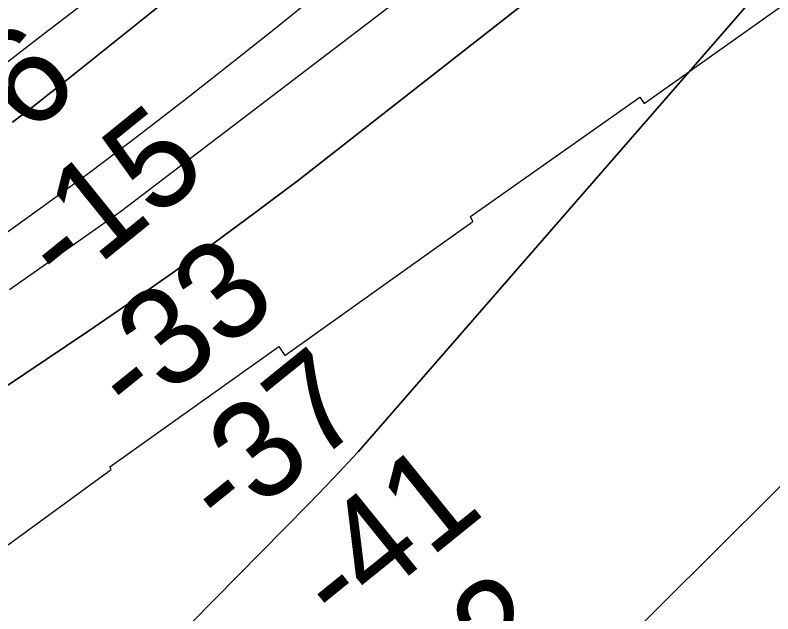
# Model space of a CAD drawing. Extents: x 3324104 to 3361979, y 612876 to 638273.
# Drawn here: x 3351732 to 3352253, y 619719 to 620131 of the extents above; entities that cross this region are included whole.
import ezdxf

# ---------------------------------------------------------------- set-up
doc = ezdxf.new("R2010")
doc.units = 0
for name, color, linetype in [('V-RIVR-EDGE', 7, 'Continuous'), ('V-RIVR-RANG', 7, 'Continuous'), ('V-RRAP-RVMT', 7, 'Continuous'), ('V-TOPO-DPTH', 7, 'Continuous'), ('V-TOPO-MAJR', 7, 'Continuous'), ('V-TOPO-MINR', 7, 'Continuous')]:
    doc.layers.add(name, color=color, linetype=linetype)

msp = doc.modelspace()

# ---------------------------------------------------------------- linework, layer by layer
at = {"layer": 'V-RIVR-EDGE'}
msp.add_spline([(3356051.95, 622889.63), (3356029.15, 622881.43), (3356012.46, 622875.66), (3355994.6, 622867.17), (3355977.52, 622859.07), (3355958.5, 622850.97), (3355948.4, 622843.24), (3355934.03, 622834.75), (3355904.12, 622817.76), (3355878.1, 622802.31), (3355856.74, 622790.34), (3355829.95, 622776.44), (3355805.11, 622765.65), (3355764.72, 622744.81), (3355744.14, 622733.61), (3355694.06, 622710.85), (3355668.43, 622698.12), (3355641.64, 622685), (3355605.15, 622669.19), (3355569.44, 622657.26), (3355539.17, 622646.47), (3355510.83, 622636.85), (3355482.11, 622628.39), (3355461.93, 622623.01), (3355442.52, 622614.14), (3355422.73, 622607.21), (3355409.53, 622603.36), (3355388.97, 622597.59), (3355371.88, 622589.49), (3355348.98, 622581.02), (3355297.71, 622547.02), (3355260.04, 622525.78), (3355211.1, 622494.49), (3355190.13, 622484.46), (3355184.7, 622482.92), (3355179.26, 622477.89), (3355174.21, 622475.58), (3355160.62, 622470.96), (3355143.54, 622463.63), (3355133.06, 622457.07), (3355125.67, 622450.49), (3355113.25, 622443.93), (3355096.93, 622433.11), (3355081.02, 622426.95), (3355064.32, 622419.23), (3355056.95, 622418.86), (3355048.8, 622414.62), (3355041.8, 622406.88), (3355036.76, 622406.5), (3355031.32, 622405.74), (3355027.05, 622404.2), (3355017.34, 622396.08), (3355010.74, 622394.93), (3355001.42, 622388.36), (3354988.6, 622379.09), (3354972.29, 622369.43), (3354947.44, 622356.31), (3354937.73, 622351.68), (3354926.08, 622343.56), (3354903.15, 622326.56), (3354891.11, 622318.06), (3354883.33, 622307.22), (3354879.44, 622304.12), (3354875.17, 622302.58), (3354867.8, 622299.11), (3354853.03, 622288.29), (3354842.54, 622279.01), (3354826.61, 622267.41), (3354807.2, 622259.71), (3354793.23, 622255.47), (3354765.68, 622249.73), (3354748.61, 622245.5), (3354734.63, 622239.33), (3354712.11, 622227.37), (3354697.74, 622218.87), (3354685.31, 622209.98), (3354640.65, 622184.5), (3354622.01, 622176.01), (3354616.19, 622175.25), (3354603.38, 622167.52), (3354578.92, 622157.11), (3354554.46, 622147.48), (3354537.39, 622142.87), (3354530.78, 622137.84), (3354500.11, 622122.79), (3354463.61, 622102.33), (3354417.79, 622078.79), (3354386.33, 622060.64), (3354340.11, 622032.44), (3354321.08, 622021.25), (3354284.96, 621998.84), (3354257, 621982.24), (3354217, 621958.68), (3354194.08, 621942.84), (3354176.99, 621931.63), (3354157.57, 621921.98), (3354141.64, 621910.39), (3354135.42, 621904.2), (3354130.36, 621897.62), (3354120.65, 621891.05), (3354103.96, 621882.95), (3354075.58, 621856.65), (3354044.89, 621835.39), (3354013.04, 621812.21), (3353971.47, 621781.67), (3353947.77, 621763.5), (3353941.17, 621763.52), (3353935.35, 621762.76), (3353929.53, 621760.06), (3353924.87, 621756.58), (3353920.59, 621751.55), (3353917.08, 621742.64), (3353910.48, 621741.49), (3353904.66, 621738.4), (3353893.78, 621731.06), (3353879.8, 621721.4), (3353866.19, 621708.64), (3353854.92, 621697.42), (3353843.26, 621687.75), (3353839.77, 621688.54), (3353831.23, 621686.23), (3353823.08, 621681.21), (3353818.03, 621677.34), (3353800.94, 621666.14), (3353790.85, 621663.06), (3353781.91, 621654.94), (3353777.63, 621651.85), (3353776.07, 621648.75), (3353775.67, 621643.71), (3353772.18, 621641), (3353755.87, 621632.13), (3353735.68, 621622.09), (3353718.58, 621608.17), (3353704.21, 621600.45), (3353694.12, 621596.6), (3353683.64, 621592.36), (3353671.21, 621584.25), (3353642.07, 621562.99), (3353598.95, 621534.01), (3353578.37, 621522.43), (3353556.23, 621507.75), (3353547.68, 621501.95), (3353525.93, 621489.21), (3353513.12, 621481.09), (3353497.18, 621468.34), (3353476.98, 621450.94), (3353453.28, 621436.65), (3353435.8, 621424.67), (3353404.72, 621401.09), (3353378.3, 621380.21), (3353361.59, 621368.62), (3353339.46, 621355.1), (3353319.65, 621342.35), (3353299.45, 621329.99), (3353283.54, 621324.6), (3353273.05, 621317.65), (3353254.77, 621295.98), (3353236.88, 621275.47), (3353219.39, 621258.83), (3353195.69, 621241.44), (3353168.49, 621221.34), (3353137.81, 621201.64), (3353112.17, 621185.03), (3353065.55, 621151.79), (3353022.05, 621122.82), (3352993.29, 621100.39), (3352956, 621073.34), (3352907.05, 621037.78), (3352853.8, 620991.77), (3352787.76, 620942.29), (3352749.68, 620913.3), (3352736.85, 620900.92), (3352733.34, 620892.79), (3352728.67, 620886.59), (3352718.96, 620881.19), (3352691.78, 620864.58), (3352660.31, 620841.78), (3352640.5, 620828.25), (3352623.39, 620811.23), (3352605.12, 620792.27), (3352593.46, 620783), (3352582.59, 620778.76), (3352566.29, 620771.43), (3352548.04, 620764.49), (3352522.41, 620750.98), (3352494.45, 620735.54), (3352482.41, 620727.04), (3352479.3, 620723.17), (3352476.96, 620717.36), (3352470.74, 620711.94), (3352455.99, 620707.33), (3352443.18, 620700.38), (3352419.1, 620685.7), (3352392.3, 620669.09), (3352362.78, 620650.94), (3352339.08, 620634.32), (3352315.38, 620615.38), (3352284.68, 620590.63), (3352258.65, 620571.31), (3352228.74, 620550.05), (3352193.39, 620527.65), (3352156.88, 620504.86), (3352131.63, 620487.47), (3352093.95, 620462.36), (3352049.28, 620432.99), (3351990.23, 620391.26), (3351936.63, 620357.26), (3351851.55, 620293.87), (3351833.29, 620281.51), (3351816.98, 620273.79), (3351794.06, 620257.95), (3351767.65, 620240.95), (3351719.86, 620206.17), (3351680.63, 620177.57), (3351657.32, 620160.56), (3351637.11, 620145.87), (3351623.13, 620135.44), (3351603.32, 620124.24), (3351588.57, 620120.01), (3351567.22, 620109.59), (3351552.08, 620103.43), (3351538.1, 620096.48), (3351523.73, 620086.43), (3351510.91, 620076.38), (3351503.52, 620069.81), (3351495.35, 620057.42), (3351486, 620042.32), (3351479.39, 620032.64), (3351469.67, 620022.58), (3351448.3, 620006.34), (3351431.59, 619994.75), (3351404.78, 619973.88), (3351377.97, 619951.84), (3351358.93, 619936.37), (3351332.12, 619915.5), (3351306.08, 619892.29), (3351274.58, 619858.25), (3351238.83, 619826.92), (3351215.12, 619805.65), (3351171.59, 619767.75), (3351145.54, 619739.51), (3351124.55, 619722.11), (3351105.9, 619707.81), (3351089.59, 619696.99), (3351079.49, 619691.2), (3351074.04, 619683.45), (3351058.1, 619666.43), (3351043.34, 619655.22), (3351015.36, 619633.96), (3350999.05, 619623.14), (3350992.05, 619617.34), (3350979.23, 619606.13), (3350966.01, 619594.53), (3350951.25, 619582.15), (3350935.7, 619567.84), (3350923.26, 619555.08), (3350910.05, 619544.25), (3350888.29, 619528.02), (3350846.74, 619504.08), (3350821.49, 619490.18), (3350811.39, 619483.61), (3350805.96, 619480.52), (3350800.9, 619473.16), (3350797.41, 619473.17), (3350793.92, 619474.35), (3350788.88, 619473.58), (3350786.93, 619472.04), (3350785.37, 619467.39), (3350785.36, 619462.73), (3350779.53, 619456.15), (3350765.93, 619445.72), (3350746.11, 619428.7), (3350722.4, 619408.98), (3350716.19, 619407.06), (3350713.08, 619403.96), (3350711.13, 619396.99), (3350708.79, 619391.57), (3350704.52, 619391.58), (3350693.26, 619385.79), (3350686.65, 619379.6), (3350679.64, 619368.37), (3350661.38, 619354.45), (3350648.56, 619344.4), (3350645.46, 619344.8), (3350638.47, 619339.39), (3350623.32, 619330.5), (3350616.33, 619326.26), (3350602.35, 619317.37), (3350598.83, 619308.85), (3350582.91, 619299.19), (3350553.77, 619276), (3350526.18, 619255.51), (3350493.55, 619231.94), (3350474.9, 619219.57), (3350474.5, 619213.76), (3350470.22, 619207.17), (3350458.96, 619202.55), (3350446.14, 619194.05), (3350441.09, 619189.79), (3350438.76, 619186.31), (3350434.48, 619180.89), (3350414.67, 619167.76), (3350401.46, 619159.26), (3350384.75, 619146.89), (3350369.6, 619133.74), (3350356.39, 619125.24), (3350350.95, 619119.05), (3350347.43, 619109.36), (3350338.1, 619097.75), (3350324.88, 619083.82), (3350308.55, 619069.9), (3350300.39, 619062.56), (3350296.13, 619062.57), (3350291.47, 619062.19), (3350274.77, 619050.6), (3350258.45, 619037.45), (3350251.84, 619032.81), (3350244.08, 619029.34), (3350233.61, 619028.21), (3350227.39, 619024.34), (3350220.39, 619016.99), (3350213, 619007.32), (3350202.12, 618996.87), (3350193.57, 618989.52), (3350179.6, 618985.29), (3350173.77, 618980.65), (3350164.84, 618977.96), (3350162.12, 618975.25), (3350159.39, 618971.38), (3350154.33, 618963.64), (3350145.78, 618953.19), (3350125.96, 618938.11), (3350102.66, 618923.05), (3350094.5, 618918.41), (3350086.34, 618913), (3350075.07, 618901.01), (3350064.19, 618892.12), (3350039.32, 618873.57), (3350021.84, 618861.59), (3350002.03, 618848.84), (3349991.94, 618844.21), (3349964.36, 618826.44), (3349938.72, 618807.11), (3349915.41, 618792.82), (3349892.5, 618778.92), (3349868.02, 618761.91), (3349852.49, 618753.03), (3349842.79, 618749.95), (3349830.35, 618739.13), (3349804.32, 618720.19), (3349777.9, 618697.76), (3349751.86, 618677.66), (3349729.72, 618661.43), (3349703.69, 618642.88), (3349678.84, 618629.75), (3349648.93, 618611.99), (3349624.46, 618594.99), (3349592.61, 618575.67), (3349570.48, 618564.87), (3349549.5, 618548.63), (3349505.21, 618518.11), (3349479.19, 618499.94), (3349471.42, 618494.53), (3349458.99, 618487.59), (3349438.4, 618472.12), (3349412.37, 618452.41), (3349379.73, 618429.61), (3349350.21, 618410.29), (3349303.2, 618374.73), (3349277.56, 618357.73), (3349263.97, 618347.29), (3349241.43, 618330.68), (3349226.67, 618319.85), (3349207.25, 618306.33), (3349193.17, 618293.54)], degree=3, dxfattribs=at)
at = {"layer": 'V-RRAP-RVMT'}
for p, q in [((3352164.48, 620070.17), (3352294.24, 620162.59)), ((3352044.88, 619992.52), (3352161.38, 620074.41)), ((3352161.38, 620074.41), (3352164.48, 620070.17)), ((3351917.24, 619896.96), (3352046.53, 619989.05)), ((3352046.53, 619989.05), (3352044.88, 619992.52)), ((3351796.76, 619820.47), (3351913.05, 619903.04)), ((3351913.05, 619903.04), (3351917.24, 619896.96)), ((3351672.84, 619727.74), (3351797.82, 619818.44)), ((3351797.82, 619818.44), (3351796.76, 619820.47))]:
    msp.add_line(p, q, dxfattribs=at)
at = {"layer": 'V-TOPO-DPTH'}
for points in [[(3353036.22, 620942.67), (3353003.24, 620918.6), (3352970.44, 620894.29), (3352937.91, 620869.63), (3352905.55, 620844.72), (3352459.62, 620497.61), (3352447.34, 620488.04), (3352435.06, 620478.45), (3352422.8, 620468.85), (3352410.55, 620459.24), (3352392.25, 620444.85), (3352389.16, 620442.42), (3352386.06, 620440), (3352382.95, 620437.58), (3352379.85, 620435.17), (3352360.2, 620419.92), (3352347.25, 620409.91), (3352334.29, 620399.91), (3352321.3, 620389.95), (3352308.3, 620380), (3351805.13, 619996.41), (3351799.27, 619992.18), (3351793.38, 619988), (3351727.81, 619942.08)], [(3353036.22, 620942.67), (3353003.24, 620918.6), (3352970.44, 620894.29), (3352937.91, 620869.63), (3352905.55, 620844.72), (3352459.62, 620497.61), (3352447.34, 620488.04), (3352435.06, 620478.45), (3352422.8, 620468.85), (3352410.55, 620459.24), (3352392.25, 620444.85), (3352389.16, 620442.42), (3352386.06, 620440), (3352382.95, 620437.58), (3352379.85, 620435.17), (3352360.2, 620419.92), (3352347.25, 620409.91), (3352334.29, 620399.91), (3352321.3, 620389.95), (3352308.3, 620380), (3351805.13, 619996.41), (3351799.27, 619992.18), (3351793.38, 619988), (3351727.81, 619942.08)], [(3351729.95, 620057.28), (3351738.1, 620063.46), (3351746.22, 620069.68), (3351754.27, 620075.98), (3351762.28, 620082.33), (3352225.26, 620452.7), (3352240.9, 620465.17), (3352256.58, 620477.61), (3352272.29, 620490), (3352288.03, 620502.36), (3352318.27, 620526.01), (3352318.91, 620526.51), (3352319.56, 620527), (3352320.87, 620527.97), (3352333.79, 620537.38), (3352340.91, 620542.55), (3352348.06, 620547.69), (3352355.23, 620552.8), (3352362.42, 620557.89), (3352890.31, 620929.69)], [(3352890.31, 620929.69), (3352362.42, 620557.89), (3352355.23, 620552.8), (3352348.06, 620547.69), (3352340.91, 620542.55), (3352333.79, 620537.38), (3352320.87, 620527.97), (3352319.56, 620527), (3352318.91, 620526.51), (3352318.27, 620526.01), (3352288.03, 620502.36), (3352272.29, 620490), (3352256.58, 620477.61), (3352240.9, 620465.17), (3352225.26, 620452.7), (3351762.28, 620082.33), (3351754.27, 620075.98), (3351746.22, 620069.68), (3351738.1, 620063.46), (3351729.95, 620057.28)], [(3351319.54, 619603.27), (3351781.82, 619913.5), (3351810.88, 619933.33), (3351839.73, 619953.46), (3351868.26, 619974.03), (3351896.58, 619994.91), (3351926.72, 620017.49), (3352384.5, 620375.72), (3352401.28, 620388.9), (3352418.1, 620402.03), (3352434.99, 620415.07), (3352451.93, 620428.05), (3352740.22, 620647.74), (3352784.16, 620681.15), (3352828.16, 620714.49), (3352872.24, 620747.72), (3352916.37, 620780.89), (3352986.62, 620833.56), (3352995.68, 620840.32), (3353004.75, 620847.07), (3353013.86, 620853.78)], [(3351319.54, 619603.27), (3351781.82, 619913.5), (3351810.88, 619933.33), (3351839.73, 619953.46), (3351868.26, 619974.03), (3351896.58, 619994.91), (3351926.72, 620017.49), (3352384.5, 620375.72), (3352401.28, 620388.9), (3352418.1, 620402.03), (3352434.99, 620415.07), (3352451.93, 620428.05), (3352740.22, 620647.74), (3352784.16, 620681.15), (3352828.16, 620714.49), (3352872.24, 620747.72), (3352916.37, 620780.89), (3352986.62, 620833.56), (3352995.68, 620840.32), (3353004.75, 620847.07), (3353013.86, 620853.78)], [(3353026.28, 620776.91), (3353006.59, 620763.44), (3352605.8, 620491.3), (3352578.11, 620472.26), (3352550.57, 620453.01), (3352523.25, 620433.44), (3352496.08, 620413.65), (3352446.4, 620377.03), (3352444.2, 620375.38), (3352442.02, 620373.71), (3352439.87, 620372), (3352437.74, 620370.27), (3351967.68, 619830.77), (3351950.86, 619812.91), (3351933.84, 619795.24), (3351916.69, 619777.68), (3351644.56, 619502.13)], [(3351644.56, 619502.13), (3351916.69, 619777.68), (3351933.84, 619795.24), (3351950.86, 619812.91), (3351967.68, 619830.77), (3352437.74, 620370.27), (3352439.87, 620372), (3352442.02, 620373.71), (3352444.2, 620375.38), (3352446.4, 620377.03), (3352496.08, 620413.65), (3352523.25, 620433.44), (3352550.57, 620453.01), (3352578.11, 620472.26), (3352605.8, 620491.3), (3353006.59, 620763.44), (3353026.28, 620776.91)]]:
    msp.add_lwpolyline(points, dxfattribs=at)
at = {"layer": 'V-TOPO-MAJR'}
msp.add_lwpolyline([(3353017.11, 620344.3), (3352996.78, 620341.39), (3352976.67, 620337.49), (3352956.92, 620332.1), (3352937.39, 620325.71), (3352894.4, 620309.83), (3352854.13, 620293.57), (3352814.62, 620275.75), (3352776.25, 620255.59), (3352738.64, 620233.87), (3352639.36, 620172.46), (3352627.55, 620164.62), (3352616.12, 620156.31), (3352605.25, 620147.27), (3352594.76, 620137.75), (3352533.52, 620078.53), (3352492.77, 620038.95), (3352452.13, 619999.27), (3352411.65, 619959.41), (3352371.29, 619919.45), (3352135.77, 619685.35)], dxfattribs=at)
at = {"layer": 'V-TOPO-MINR'}
for points in [[(3353397.75, 621335.43), (3352925.65, 620986.72), (3352918.35, 620981.35), (3352911.02, 620976.01), (3352903.67, 620970.7), (3352896.3, 620965.42), (3352780.91, 620883.2), (3352715.88, 620836.76), (3352650.91, 620790.24), (3352586.04, 620743.58), (3352521.23, 620696.84), (3352324.5, 620554.66), (3352315.95, 620548.43), (3352307.43, 620542.15), (3352298.96, 620535.81), (3352290.52, 620529.43), (3351865.02, 620204.85), (3351841.53, 620186.91), (3351818.06, 620168.95), (3351794.61, 620150.96), (3351771.18, 620132.95), (3351747.74, 620114.93), (3351724.29, 620096.94)], [(3353027.88, 620990.37), (3352965.08, 620945.68), (3352954.55, 620938.16), (3352944.03, 620930.6), (3352933.54, 620923.01), (3352923.07, 620915.39), (3352827.91, 620845.83), (3352770.08, 620803.13), (3352712.53, 620760.05), (3352655.41, 620716.42), (3352598.57, 620672.42), (3352389.14, 620508.66), (3352371.71, 620494.96), (3352354.34, 620481.19), (3352337.03, 620467.32), (3352319.78, 620453.39), (3351913.24, 620123.76), (3351881.1, 620098.28), (3351848.86, 620072.92), (3351848.05, 620072.28), (3351815.98, 620047.56), (3351783.66, 620023.17), (3351750.98, 619999.25), (3351718.07, 619975.66)], [(3353036.22, 620942.67), (3353003.24, 620918.6), (3352970.44, 620894.29), (3352937.91, 620869.63), (3352905.55, 620844.72), (3352459.62, 620497.61), (3352447.34, 620488.04), (3352435.06, 620478.45), (3352422.8, 620468.85), (3352410.55, 620459.24), (3352392.25, 620444.85), (3352389.16, 620442.42), (3352386.06, 620440), (3352382.95, 620437.58), (3352379.85, 620435.17), (3352360.2, 620419.92), (3352347.25, 620409.91), (3352334.29, 620399.91), (3352321.3, 620389.95), (3352308.3, 620380), (3351805.13, 619996.41), (3351799.27, 619992.18), (3351793.38, 619988), (3351727.81, 619942.08)], [(3352890.31, 620929.69), (3352362.42, 620557.89), (3352355.23, 620552.8), (3352348.06, 620547.69), (3352340.91, 620542.55), (3352333.79, 620537.38), (3352320.87, 620527.97), (3352319.56, 620527), (3352318.91, 620526.51), (3352318.27, 620526.01), (3352288.03, 620502.36), (3352272.29, 620490), (3352256.58, 620477.61), (3352240.9, 620465.17), (3352225.26, 620452.7), (3351762.28, 620082.33), (3351754.27, 620075.98), (3351746.22, 620069.68), (3351738.1, 620063.46), (3351729.95, 620057.28)], [(3353013.86, 620853.78), (3353004.75, 620847.07), (3352995.68, 620840.32), (3352986.62, 620833.56), (3352916.37, 620780.89), (3352872.24, 620747.72), (3352828.16, 620714.49), (3352784.16, 620681.15), (3352740.22, 620647.74), (3352451.93, 620428.05), (3352434.99, 620415.07), (3352418.1, 620402.03), (3352401.28, 620388.9), (3352384.5, 620375.72), (3351926.72, 620017.49), (3351896.58, 619994.91), (3351868.26, 619974.03), (3351839.73, 619953.46), (3351810.88, 619933.33), (3351781.82, 619913.5), (3351319.54, 619603.27)], [(3353026.28, 620776.91), (3353006.59, 620763.44), (3352605.8, 620491.3), (3352578.11, 620472.26), (3352550.57, 620453.01), (3352523.25, 620433.44), (3352496.08, 620413.65), (3352446.4, 620377.03), (3352444.2, 620375.38), (3352442.02, 620373.71), (3352439.87, 620372), (3352437.74, 620370.27), (3351967.68, 619830.77), (3351950.86, 619812.91), (3351933.84, 619795.24), (3351916.69, 619777.68), (3351644.56, 619502.13)]]:
    msp.add_lwpolyline(points, dxfattribs=at)

# ---------------------------------------------------------------- texts
at = {"layer": 'V-RIVR-RANG'}
for s, p in [('-6', (3351716.19, 620028.43)), ('-15', (3351765.72, 619939.89)), ('-33', (3351813.61, 619850.02)), ('-37', (3351876.68, 619772.41)), ('-41', (3351955.14, 619707.24)), ('-42', (3352004.87, 619618.87))]:
    msp.add_text(s, height=67, rotation=38.9415, dxfattribs=at).set_placement(p)

doc.saveas('drawing.dxf')
